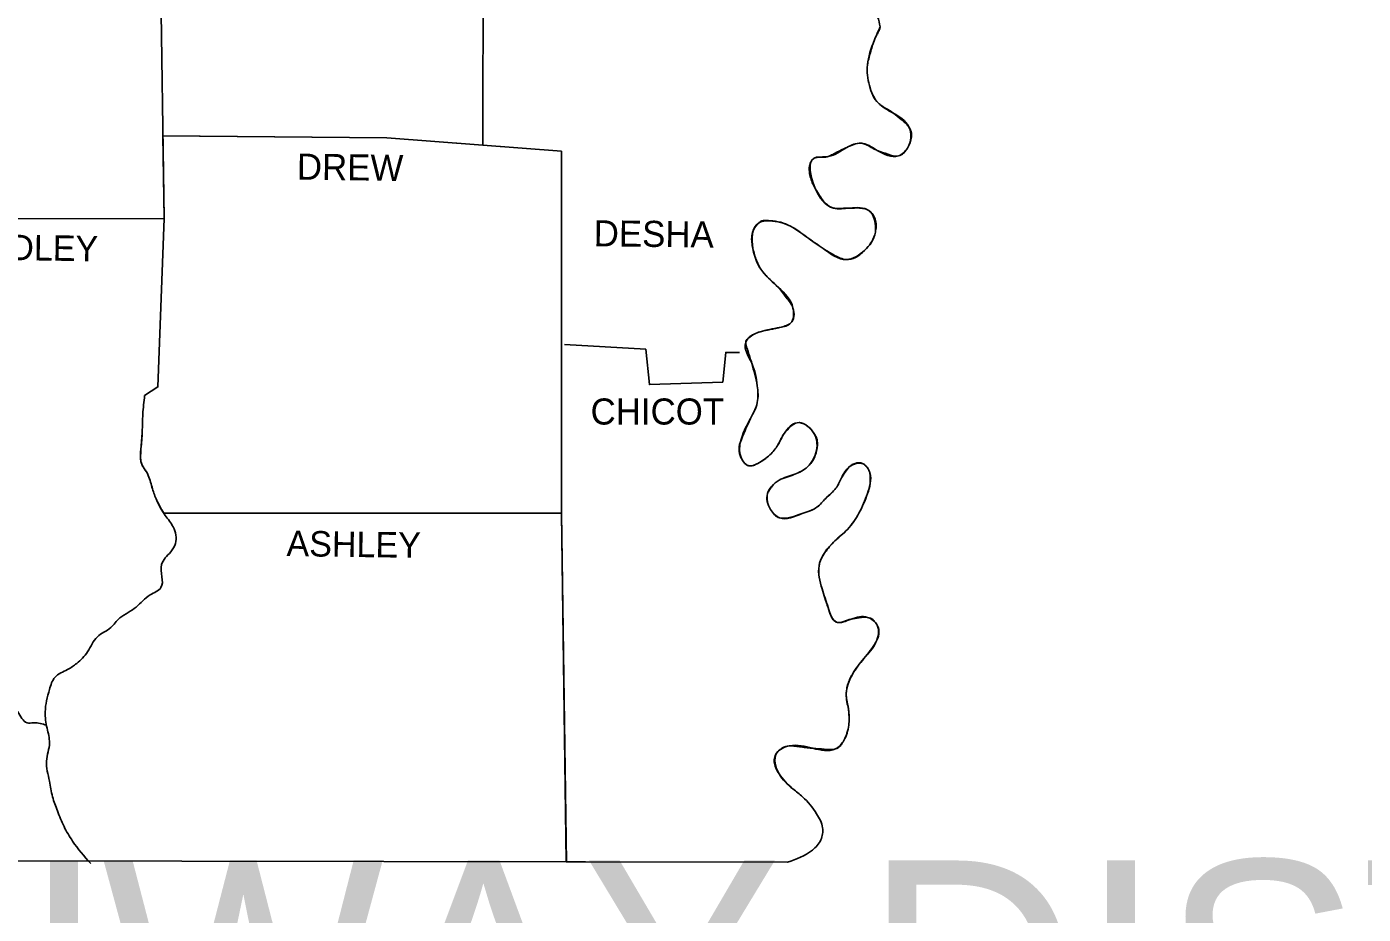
# Model space of a CAD drawing. Extents: x 3046 to 131673, y -8885 to 10756.
# Drawn here: x 28781 to 30939, y 4994 to 6426 of the extents above; entities that cross this region are included whole.
import ezdxf

# ---------------------------------------------------------------- set-up
doc = ezdxf.new("R2010")
doc.units = 0
for name, color, linetype in [('1', 7, 'Continuous'), ('2', 7, 'Continuous'), ('R_Annotation', 7, 'Continuous')]:
    doc.layers.add(name, color=color, linetype=linetype)

msp = doc.modelspace()

# ---------------------------------------------------------------- linework, layer by layer
at = {"layer": '1'}
for points in [[(29016.4, 6645.9), (29017.4, 6523.6), (28996.8, 6522.6), (29002.7, 6116.6)], [(29677.8, 6594.1), (29666.1, 6567.6), (29614.2, 6562.8), (29611.3, 6527.5), (29518.3, 6527.5), (29517.3, 6235)], [(28999.8, 6249.7), (29362.7, 6246.7), (29644.5, 6225.2)], [(29644.5, 6225.2), (29644.5, 5640.1), (29652.4, 5077.5)], [(28560.5, 6115.6), (29002.7, 6116.6)], [(29002.7, 6116.6), (28992.9, 5844.6), (28971.4, 5830.9)], [(29649.4, 5913.1), (29780.5, 5905.3), (29786.4, 5848.5), (29904.8, 5852.4), (29909.7, 5900.4), (29932.2, 5900.4)], [(26421.7, 5874.9), (26423.6, 5083.4), (30009.5, 5077.5)], [(29002.3, 5641.1), (29644.5, 5641.1)]]:
    msp.add_lwpolyline(points, dxfattribs=at)
for points in [[(30833.3, 7720.2), (30810.8, 7691.8), (30777.5, 7709.4), (30777.5, 7732.9), (30782.4, 7757.4), (30770.7, 7773), (30750.1, 7766.2), (30750.1, 7735.9), (30748.2, 7706.5), (30742.3, 7664.4), (30756, 7651.7), (30787.3, 7647.8), (30809.8, 7641.9), (30823.5, 7619.4), (30822.5, 7592), (30811.8, 7565.6), (30796.1, 7544.1), (30771.7, 7536.3), (30752.1, 7549), (30744.3, 7574.4), (30735.5, 7596.9), (30718.8, 7613.6), (30701.2, 7595), (30697.3, 7560.7), (30698.3, 7531.4), (30698.3, 7491.3), (30723.7, 7464.8), (30739.4, 7434.5), (30734.5, 7407.1), (30715.9, 7374.8), (30708.1, 7346.5), (30700.2, 7308.3), (30701.2, 7266.2), (30694.4, 7225.1), (30680.7, 7197.7), (30655.2, 7175.2), (30638.6, 7160.6), (30624.9, 7145.9), (30618, 7116.5), (30613.2, 7096), (30594.6, 7071.5), (30579.9, 7069.6), (30568.1, 7079.4), (30564.2, 7096), (30564.2, 7112.6), (30556.4, 7129.3), (30531.9, 7136.1), (30512.4, 7135.1), (30503.6, 7121.4), (30516.3, 7083.3), (30521.2, 7058.8), (30514.3, 7025.5), (30518.2, 7021.6), (30483, 7003), (30454.7, 7000.1), (30431.2, 6993.3), (30408.7, 6978.6), (30397.9, 6957.1), (30382.2, 6939.4), (30368.6, 6922.8), (30350, 6915), (30329.4, 6918.9), (30302, 6921.8), (30286.4, 6902.3), (30291.3, 6873.9), (30309.8, 6857.3), (30337.2, 6849.4), (30365.6, 6851.4), (30393, 6854.3), (30418.4, 6840.6), (30413.6, 6814.2), (30389.1, 6801.5), (30352.9, 6797.6), (30323.5, 6800.5), (30288.3, 6792.7), (30270.7, 6770.2), (30280.5, 6735.9), (30318.7, 6722.2), (30336.3, 6689.9), (30337.2, 6659.6), (30324.5, 6619.5), (30306.9, 6600.9), (30272.7, 6593.1), (30246.2, 6588.2), (30242.3, 6543.2), (30230.6, 6520.7), (30210, 6513.8), (30180.7, 6528.5), (30163.1, 6535.4), (30141.6, 6545.1), (30114.2, 6561.8), (30093.6, 6558.8), (30099.5, 6515.8), (30101.4, 6513.8), (30124.9, 6481.5), (30148.4, 6456.1), (30159.2, 6425.8)], [(30159.2, 6425.8), (30149.4, 6403.3), (30138.6, 6364.1), (30141.6, 6330.9), (30156.2, 6302.5), (30179.7, 6286.8), (30205.2, 6264.3), (30203.2, 6230.1), (30188.5, 6217.4), (30154.3, 6226.2), (30127.9, 6237.9), (30105.4, 6231.1), (30075, 6216.4), (30052.5, 6213.5), (30053.5, 6166.5), (30083.8, 6133.2), (30110.3, 6133.2), (30140.6, 6129.3), (30151.3, 6094.1), (30133.7, 6064.7), (30104.4, 6050.1), (30067.2, 6067.7), (30040.8, 6086.3), (30014.4, 6103.9), (29981.1, 6112.7), (29962.5, 6108.8), (29953.7, 6067.7), (29969.4, 6030.5), (29994.8, 6005.1), (30018.3, 5971.8), (30014.4, 5947.3), (29996.8, 5940.5), (29965.4, 5933.6), (29946.9, 5923.9), (29942, 5916), (29951.7, 5882.8), (29960.6, 5846.6), (29960.6, 5819.2), (29949.8, 5793.7), (29933.2, 5754.6), (29935.1, 5729.2), (29946.9, 5717.4), (29961.5, 5721.3), (29981.1, 5735), (29993.8, 5750.7), (30004.6, 5770.2), (30025.1, 5786.9), (30050.6, 5772.2), (30056.4, 5741.9), (30041.8, 5715.5), (30021.2, 5703.7), (29995.8, 5693.9), (29977.2, 5672.4), (29982.1, 5647), (29996.8, 5633.3), (30033, 5640.1), (30057.4, 5650.9), (30071.1, 5664.6), (30087.7, 5681.2), (30096.6, 5697.8), (30109.3, 5715.5), (30131.8, 5720.3), (30142.5, 5705.7), (30138.6, 5672.4), (30124.9, 5641.1), (30106.3, 5614.7), (30085.8, 5596.1), (30060.4, 5556), (30065.2, 5518.8), (30075, 5488.5), (30088.7, 5465), (30112.2, 5469.9), (30138.6, 5472.8), (30154.3, 5460.1), (30152.3, 5432.7), (30132.8, 5406.3), (30114.2, 5380.8), (30104.4, 5345.6), (30108.3, 5321.2), (30108.3, 5298.7), (30100.5, 5274.2), (30086.8, 5260.5), (30050.6, 5261.5), (30012.4, 5265.4), (29991.9, 5253.6), (29995.8, 5220.4), (30018.3, 5195.9), (30033.9, 5183.2), (30056.4, 5155.8), (30066.2, 5133.3), (30063.3, 5113.7), (30049.6, 5097.1), (30009.5, 5077.5)], [(28971.4, 5830.9), (28968.5, 5800.6), (28967.5, 5772.2), (28965.5, 5744.8), (28965.5, 5724.3), (28977.3, 5701.8), (28984.1, 5680.2), (28991, 5661.6), (29004.7, 5637.2), (29017.4, 5618.6), (29021.3, 5592.2), (29013.5, 5578.5), (28998.8, 5557.9), (28997.8, 5520.8), (28980.2, 5509), (28957.7, 5489.4), (28945, 5480.6), (28931.3, 5471.8), (28916.6, 5456.2), (28895.1, 5441.5), (28879.4, 5417), (28861.8, 5398.5), (28847.1, 5388.7), (28826.6, 5375.9), (28817.8, 5356.4), (28810.9, 5320.2), (28813.9, 5293.8), (28817.8, 5270.3), (28812.9, 5240.9), (28817.8, 5208.6), (28822.7, 5183.2), (28830.5, 5160.7), (28841.3, 5135.3), (28855, 5111.8), (28884.3, 5075.6)], [(27995.9, 5604.9), (28011.6, 5615.7), (28026.2, 5621.5), (28040.9, 5618.6), (28056.6, 5616.6), (28070.3, 5618.6), (28087.9, 5615.7), (28102.6, 5606.9), (28119.2, 5600), (28135.8, 5600), (28150.5, 5600), (28163.2, 5591.2), (28186.7, 5592.2), (28206.3, 5600), (28225.8, 5605.9), (28252.3, 5608.8), (28275.7, 5592.2), (28292.4, 5578.5), (28306.1, 5562.8), (28315.9, 5545.2), (28326.6, 5535.4), (28344.2, 5528.6), (28357.9, 5525.6), (28374.6, 5520.8), (28383.4, 5516.8), (28391.2, 5498.2), (28403.9, 5472.8), (28428.4, 5464), (28458.7, 5475.7), (28483.2, 5482.6), (28500.8, 5488.5), (28511.5, 5492.4), (28521.3, 5493.4), (28518.4, 5495.3), (28530.1, 5498.2), (28540.9, 5490.4), (28547.7, 5479.7), (28559.5, 5464), (28570.2, 5450.3), (28581, 5445.4), (28591.8, 5451.3), (28606.4, 5446.4), (28619.2, 5441.5), (28633.8, 5437.6), (28646.6, 5436.6), (28663.2, 5432.7), (28675.9, 5425.8), (28687.6, 5419), (28699.4, 5406.3), (28711.1, 5386.7), (28715, 5371.1), (28728.7, 5355.4), (28741.5, 5355.4), (28760, 5330), (28766.9, 5320.2), (28781.6, 5302.6), (28792.3, 5302.6), (28812.9, 5298.7)]]:
    msp.add_spline(points, degree=3, dxfattribs=at)
at = {"layer": 'R_Annotation'}
for p, q in [((29362.7, 6246.7), (29000.8, 6249.7)), ((29000.8, 6249.7), (29002.7, 6116.6)), ((29517.3, 6234.9), (29644.5, 6225.2)), ((29644.5, 5640.1), (29644.5, 6225.2)), ((29002.3, 5641.1), (29644.5, 5640.1))]:
    msp.add_line(p, q, dxfattribs=at)
for points in [[(29677.8, 6594.1), (29666.1, 6567.6), (29614.2, 6562.8), (29611.3, 6527.5), (29518.3, 6527.5), (29517.3, 6235)], [(29644.5, 6225.2), (29517.3, 6234.9), (29362.7, 6246.7)], [(29517.3, 6235), (29517.3, 6234.9)], [(29644.5, 6225.2), (29644.5, 5640.1), (29652.3, 5078.1)], [(29002.7, 6116.6), (28992.9, 5844.6), (28971.4, 5830.9)], [(29652.3, 5078.1), (29652.4, 5078.1), (30009.5, 5077.5)]]:
    msp.add_lwpolyline(points, dxfattribs=at)
for points in [[(29976.7, 6022.4), (29969.4, 6030.5), (29959.3, 6048.7), (29953.7, 6067.7), (29951.9, 6077.9), (29951.9, 6088.4), (29955, 6098.9), (29962.5, 6108.8), (29964.8, 6110.6), (29967.1, 6111.9), (29971.8, 6113.2), (29981.1, 6112.7), (29989.5, 6111.6), (29998, 6110.1), (30014.4, 6103.9), (30040.8, 6086.3), (30067.2, 6067.7), (30085.6, 6056.9), (30104.4, 6050.1), (30119.1, 6053.3), (30133.7, 6064.7), (30140.4, 6071.8), (30145.4, 6079.1), (30151.3, 6094.1), (30152.6, 6103.2), (30151.6, 6113.1), (30147.8, 6122.3), (30140.6, 6129.3), (30136.8, 6131.2), (30133, 6132.4), (30125.5, 6133.3), (30110.3, 6133.2), (30103.7, 6133.2), (30097, 6132.6), (30090.4, 6132.4), (30083.8, 6133.2), (30078.6, 6135.2), (30073.9, 6138.2), (30066, 6146.4), (30053.5, 6166.5), (30050.6, 6172), (30044.9, 6191.5), (30045.8, 6204.1), (30048.3, 6209.3), (30052.5, 6213.5), (30055.1, 6214.8), (30057.8, 6215.4), (30063.7, 6215.5), (30069.5, 6215.3), (30075, 6216.4), (30082.6, 6219.9), (30090.1, 6223.7), (30097.6, 6227.5), (30105.4, 6231.1), (30116.6, 6235.8), (30127.9, 6237.9), (30131.2, 6237.4), (30134.5, 6236.4), (30141.1, 6233.1), (30147.7, 6229.3), (30154.3, 6226.2), (30171.3, 6220.1), (30188.5, 6217.4), (30196.7, 6221.6), (30200.1, 6225.7), (30203.2, 6230.1), (30207.5, 6238.6), (30209.6, 6247.9), (30209, 6256.9), (30205.2, 6264.3), (30193, 6276.2), (30179.7, 6286.8), (30173.9, 6290.8), (30167.8, 6294.3), (30161.9, 6298), (30156.2, 6302.5), (30141.6, 6330.9), (30138.6, 6364.1), (30143.3, 6383.9), (30149.4, 6403.3), (30151.8, 6409), (30154.6, 6414.6), (30157.3, 6420.2), (30159.2, 6425.8)], [(30142.4, 5706.4), (30138.4, 5714.2), (30135.3, 5717.6), (30131.8, 5720.3), (30126.3, 5722.2), (30120.1, 5721.7), (30114.1, 5719.3), (30109.3, 5715.5), (30102.5, 5706.9), (30096.6, 5697.8), (30094.4, 5693.6), (30092.6, 5689.2), (30087.7, 5681.2), (30071.1, 5664.6), (30057.4, 5650.9), (30033, 5640.1), (30014.9, 5634.3), (30005.7, 5632.8), (29996.8, 5633.3), (29988.5, 5638.3), (29982.1, 5647), (29976.5, 5659.8), (29977.2, 5672.4), (29980.3, 5678.6), (29984.5, 5684.5), (29995.8, 5693.9), (30002.1, 5696.9), (30008.5, 5699.1), (30014.9, 5701.2), (30021.2, 5703.7), (30041.8, 5715.5), (30056.4, 5741.9), (30057.7, 5749.3), (30057.5, 5757), (30055.3, 5764.7), (30050.6, 5772.2), (30044.4, 5778.7), (30037.9, 5783.9), (30025.1, 5786.9), (30014.4, 5780.6), (30004.6, 5770.2), (30001.4, 5765.4), (29998.9, 5760.4), (29996.6, 5755.4), (29993.8, 5750.7), (29981.1, 5735), (29961.5, 5721.3), (29954.3, 5717.9), (29946.9, 5717.4), (29940.1, 5721.8), (29935.1, 5729.2), (29932.6, 5735.5), (29931.4, 5742), (29931.5, 5748.5), (29933.2, 5754.6), (29949.8, 5793.7), (29960.6, 5819.2), (29960.6, 5846.6), (29951.7, 5882.8), (29949.3, 5891.1), (29946.6, 5899.5), (29944, 5907.7), (29942, 5916), (29943.2, 5920.2), (29944.9, 5922.1), (29946.9, 5923.9), (29965.4, 5933.6), (29973.2, 5935.6), (29981.1, 5937.2), (29988.9, 5938.7), (29996.8, 5940.5), (30005.8, 5943), (30010.1, 5944.8), (30014.4, 5947.3), (30018.3, 5971.8), (30007.5, 5988.8), (29994.8, 6005.1), (29985.9, 6013.9), (29976.7, 6022.4)], [(28971.4, 5830.9), (28968.5, 5800.6), (28967.5, 5772.2), (28965.5, 5744.8), (28965, 5734.5), (28965, 5729.4), (28965.5, 5724.3), (28967.5, 5718.3), (28970.8, 5712.8), (28974.5, 5707.5), (28977.3, 5701.8), (28984.1, 5680.2), (28991, 5661.6), (29002.3, 5641.1)], [(30009.5, 5077.5), (30049.6, 5097.1), (30063.3, 5113.7), (30066.2, 5133.3), (30056.4, 5155.8), (30033.9, 5183.2), (30018.3, 5195.9), (29995.8, 5220.4), (29988.3, 5236.8), (29988.3, 5245.7), (29991.9, 5253.6), (29996.3, 5258.3), (30001.2, 5262.1), (30012.4, 5265.4), (30021.9, 5264.8), (30031.5, 5263.6), (30041, 5262.4), (30050.6, 5261.5), (30068.7, 5260), (30086.8, 5260.5), (30094.8, 5265.4), (30097.8, 5269.6), (30100.5, 5274.2), (30108.3, 5298.7), (30108.3, 5321.2), (30107.5, 5327.3), (30106.2, 5333.4), (30105, 5339.5), (30104.4, 5345.6), (30104.8, 5354.8), (30106.5, 5363.9), (30114.2, 5380.8), (30132.8, 5406.3), (30152.3, 5432.7), (30157.1, 5446), (30154.3, 5460.1), (30151.3, 5464.7), (30147.6, 5468.7), (30138.6, 5472.8), (30125.4, 5472), (30112.2, 5469.9), (30106.3, 5468.2), (30100.3, 5465.9), (30094.5, 5464.4), (30088.7, 5465), (30085.8, 5466.5), (30083.4, 5468.8), (30079.9, 5474.7), (30075, 5488.5), (30065.2, 5518.8), (30060.7, 5537.4), (30060.4, 5556), (30061.8, 5561.6), (30063.9, 5567), (30070, 5577.3), (30085.8, 5596.1), (30090.9, 5601), (30096.2, 5605.4), (30101.5, 5609.8), (30106.3, 5614.7), (30124.9, 5641.1), (30138.6, 5672.4), (30142.8, 5688.9), (30142.5, 5705.7), (30142.4, 5706.4)]]:
    msp.add_spline(points, degree=3, dxfattribs=at)

# ---------------------------------------------------------------- texts
at = {"layer": '2'}
for s, height, rotation, p in [('DREW', 42.06, 359.2258, (29217, 6179.2)), ('DESHA', 42.06, 359.3704, (29696.4, 6071.6)), ('BRADLEY', 41.08, 359.1449, (28639.7, 6051)), ('ASHLEY', 41.09, 359.2361, (29200.3, 5571.6))]:
    msp.add_text(s, height=height, rotation=rotation, dxfattribs=at).set_placement(p)
for s, height, p in [('CHICOT', 42.07, (29691.5, 5783.9)), ('ARKANSAS HIGHWAY DISTRICT 2', 360, (24943.9, 4720.5))]:
    msp.add_text(s, height=height, dxfattribs=at).set_placement(p)

doc.saveas('drawing.dxf')
